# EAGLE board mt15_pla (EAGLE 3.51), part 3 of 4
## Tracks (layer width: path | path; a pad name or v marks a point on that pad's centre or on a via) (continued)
N$24  (via drill 0.61 pad 1.02)
  Top 0.305: 107.62,6.6 107.62,6.97 v107.95,7.3
  Bottom 0.305: J26. 107.63,6.99 v107.95,7.3
N$25  (via drill 0.61 pad 1.02)
  Top 0.305: 73.33,6.6 73.33,6.97 v73.66,7.3
  Bottom 0.305: J17. 73.34,6.99 v73.66,7.3
N$26  (via drill 0.61 pad 1.02)
  Top 0.305: 77.14,6.6 77.14,6.97 v77.47,7.3
  Bottom 0.305: J18. 77.15,6.99 v77.47,7.3
N$27  (via drill 0.61 pad 1.02)
  Top 0.305: 80.95,6.6 80.95,6.97 v81.28,7.3
  Bottom 0.305: J19. 80.96,6.99 v81.28,7.3
N$28  (via drill 0.61 pad 1.02)
  Top 0.305: 84.76,6.6 84.76,6.97 v85.09,7.3
  Bottom 0.305: J20. 84.77,6.99 v85.09,7.3
N$29  (via drill 0.61 pad 1.02)
  Top 0.305: 88.57,6.6 88.57,6.97 v88.9,7.3
  Bottom 0.305: J21. 88.58,6.99 v88.9,7.3
N$30  (via drill 0.61 pad 1.02)
  Top 0.305: 92.38,6.6 92.38,6.97 v92.71,7.3
  Bottom 0.305: J22. 92.39,6.99 v92.71,7.3
N$31  (via drill 0.61 pad 1.02)
  Top 0.305: 96.19,6.6 96.19,6.97 v96.52,7.3
  Bottom 0.305: J23. 96.2,6.99 v96.52,7.3
N$32  (via drill 0.61 pad 1.02)
  Top 0.305: 100,6.6 100,6.97 v100.33,7.3
  Bottom 0.305: J24. 100.01,6.99 v100.33,7.3
N$33  (via drill 0.61 pad 1.02)
  Top 0.305: 103.81,6.6 103.81,6.97 v104.14,7.3
  Bottom 0.305: J25. 103.82,6.99 v104.14,7.3
N$34  (via drill 0.61 pad 1.02)
  Top 0.406: 53.03,12.45 53.03,12.39 v52.7,12.06
  Bottom 0.406: J40. 53.02,12.38 v52.7,12.06
N$35  (via drill 0.61 pad 1.02)
  Top 0.406: 49.23,12.45 49.23,12.39 v48.9,12.06
  Bottom 0.406: J39. 49.21,12.38 v48.9,12.06
N$36  (via drill 0.61 pad 1.02)
  Top 0.406: 45.41,12.45 45.41,12.39 v45.09,12.06
  Bottom 0.406: J38. 45.4,12.38 v45.09,12.06
N$37  (via drill 0.61 pad 1.02)
  Top 0.406: 22.55,12.45 22.55,12.39 v22.23,12.06
  Bottom 0.406: J32. 22.54,12.38 v22.23,12.06
N$38  (via drill 0.61 pad 1.02)
  Top 0.406: 18.75,12.45 18.75,12.39 v18.41,12.06
  Bottom 0.406: J31. 18.73,12.38 v18.41,12.06
N$39  (via drill 0.61 pad 1.02)
  Top 0.406: 14.94,12.45 14.94,12.39 v14.61,12.06
  Bottom 0.406: J30. 14.92,12.38 v14.61,12.06
N$40  (via drill 0.61 pad 1.02)
  Top 0.406: 26.36,12.45 26.36,12.39 v26.04,12.06
  Bottom 0.406: J33. 26.35,12.38 v26.04,12.06
N$41  (via drill 0.61 pad 1.02)
  Top 0.406: 30.18,12.45 30.18,12.39 v29.84,12.06
  Bottom 0.406: J34. 30.16,12.38 v29.84,12.06
N$42  (via drill 0.61 pad 1.02)
  Top 0.406: 33.98,12.45 33.98,12.39 v33.66,12.06
  Bottom 0.406: J35. 33.97,12.38 v33.66,12.06
N$43  (via drill 0.61 pad 1.02)
  Top 0.406: 37.8,12.45 37.8,12.39 v37.47,12.06
  Bottom 0.406: J36. 37.78,12.38 v37.47,12.06
N$44  (via drill 0.61 pad 1.02)
  Top 0.406: 41.6,12.45 41.6,12.39 v41.27,12.06
  Bottom 0.406: J37. 41.59,12.38 v41.27,12.06
N$45  (via drill 0.61 pad 1.02)
  Top 0.305: 105.74,11.81 105.74,11.44 v105.41,11.11
  Bottom 0.305: J52. 105.73,11.43 v105.41,11.11
N$46  (via drill 0.61 pad 1.02)
  Top 0.305: 71.45,11.81 71.12,11.48 v71.12,11.11
  Bottom 0.305: J43. 71.44,11.11 v71.12,11.11
N$47  (via drill 0.61 pad 1.02)
  Top 0.305: 75.26,11.81 74.93,11.48 v74.93,11.11
  Bottom 0.305: J44. 75.25,11.11 v74.93,11.11
N$48  (via drill 0.61 pad 1.02)
  Top 0.305: 79.07,11.81 78.74,11.48 v78.74,11.11
  Bottom 0.305: J45. 79.06,11.11 v78.74,11.11
N$49  (via drill 0.61 pad 1.02)
  Top 0.305: 82.88,11.81 82.88,11.44 v82.55,11.11
  Bottom 0.305: J46. 82.87,11.43 v82.55,11.11
N$50  (via drill 0.61 pad 1.02)
  Top 0.305: 86.69,11.81 86.69,11.44 v86.36,11.11
  Bottom 0.305: J47. 86.68,11.43 v86.36,11.11
N$51  (via drill 0.61 pad 1.02)
  Top 0.305: 90.5,11.81 90.5,11.44 v90.17,11.11
  Bottom 0.305: J48. 90.49,11.43 v90.17,11.11
N$52  (via drill 0.61 pad 1.02)
  Top 0.305: 94.31,11.81 94.31,11.44 v93.98,11.11
  Bottom 0.305: J49. 94.3,11.43 v93.98,11.11
N$53  (via drill 0.61 pad 1.02)
  Top 0.305: 98.12,11.81 98.12,11.44 v97.79,11.11
  Bottom 0.305: J50. 98.11,11.43 v97.79,11.11
N$54  (via drill 0.61 pad 1.02)
  Top 0.305: 101.93,11.81 101.93,11.44 v101.6,11.11
  Bottom 0.305: J51. 101.92,11.43 v101.6,11.11
N$55  (via drill 0.61 pad 1.02)
  Top 0.406: 7.92,14.86 7.92,14.91 v8.26,15.24
  Bottom 0.406: J53. 7.94,14.92 v8.26,15.24
N$56  (via drill 0.61 pad 1.02)
  Top 0.406: 11.73,14.86 11.73,14.91 v12.06,15.24
  Bottom 0.406: J54. 11.75,14.92 v12.06,15.24
N$57  (via drill 0.61 pad 1.02)
  Top 0.406: 15.54,14.86 15.54,14.91 v15.88,15.24
  Bottom 0.406: J55. 15.56,14.92 v15.88,15.24
N$58  (via drill 0.61 pad 1.02)
  Top 0.305: 71.4,14.86 71.4,13.65 71.75,13.65 | 71.75,13.65 75.25,13.65 | 75.25,13.65 79.06,13.65 | 75.21,14.86 75.25,14.82 75.25,13.65 | 79.02,14.86 79.06,14.82 79.06,13.65 | 71.75,13.65 71.12,13.65 v70.17,14.61 | 110.11,14.61 109.16,13.65 105.73,13.65 | 79.06,13.65 82.87,13.65 | 82.87,13.65 86.68,13.65 | 86.68,13.65 90.49,13.65 | 90.49,13.65 94.3,13.65 | 94.3,13.65 98.11,13.65 | 98.11,13.65 101.92,13.65 | 101.92,13.65 105.73,13.65 | 82.83,14.86 82.87,14.86 82.87,13.65 | 86.64,14.86 86.68,14.86 86.68,13.65 | 90.45,14.86 90.49,14.86 90.49,13.65 | 94.26,14.86 94.3,14.86 94.3,13.65 | 98.07,14.86 98.11,14.86 98.11,13.65 | 105.69,14.86 105.73,14.86 105.73,13.65 | 101.88,14.86 101.92,14.86 101.92,13.65
  Bottom 0.305: 6.22,14.92 6.35,14.92 6.35,16.51 10.16,16.51 | 10.16,16.51 13.97,16.51 | 13.97,16.51 17.78,16.51 | 17.78,16.51 21.59,16.51 | 21.59,16.51 25.4,16.51 | 25.4,16.51 29.21,16.51 | 29.21,16.51 33.02,16.51 | 33.02,16.51 36.83,16.51 | 36.83,16.51 40.64,16.51 | 40.64,16.51 44.45,16.51 | 44.45,16.51 48.26,16.51 | 48.26,16.51 52.07,16.51 | 52.07,16.51 55.88,16.51 | 55.88,16.51 59.69,16.51 | 59.69,16.51 63.5,16.51 | 63.37,14.92 63.5,14.92 63.5,16.51 | 59.56,14.92 59.69,14.92 59.69,16.51 | 55.75,14.92 55.88,14.92 55.88,16.51 | 51.94,14.92 52.07,14.92 52.07,16.51 | 48.13,14.92 48.26,14.92 48.26,16.51 | 44.32,14.92 44.45,14.92 44.45,16.51 | 40.51,14.92 40.64,14.92 40.64,16.51 | 36.7,14.92 36.83,14.92 36.83,16.51 | 32.89,14.92 33.02,14.92 33.02,16.51 | 29.08,14.92 29.21,14.92 29.21,16.51 | 25.27,14.92 25.4,14.92 25.4,16.51 | 21.46,14.92 21.59,14.92 21.59,16.51 | 10.03,14.92 10.16,14.92 10.16,16.51 | 13.84,14.92 13.97,14.92 13.97,16.51 | 17.65,14.92 17.78,14.92 17.78,16.51 | 63.5,16.51 68.26,16.51 v70.17,14.61
N$59  (via drill 0.61 pad 1.02)
  Top 0.406: 65.08,14.86 65.08,14.91 v65.41,15.24
  Bottom 0.406: J68. 65.09,14.92 v65.41,15.24
N$60  (via drill 0.61 pad 1.02)
  Top 0.406: 61.27,14.86 61.27,14.91 v61.59,15.24
  Bottom 0.406: J67. 61.28,14.92 v61.59,15.24
N$61  (via drill 0.61 pad 1.02)
  Top 0.406: 57.45,14.86 57.45,14.91 v57.78,15.24
  Bottom 0.406: J66. 57.47,14.92 v57.78,15.24
N$62  (via drill 0.61 pad 1.02)
  Top 0.406: 53.65,14.86 53.65,14.91 v53.98,15.24
  Bottom 0.406: J65. 53.66,14.92 v53.98,15.24
N$63  (via drill 0.61 pad 1.02)
  Top 0.406: 49.84,14.86 49.84,14.91 v50.16,15.24
  Bottom 0.406: J64. 49.85,14.92 v50.16,15.24
N$64  (via drill 0.61 pad 1.02)
  Top 0.406: 26.98,14.86 26.98,14.91 v27.3,15.24
  Bottom 0.406: J58. 26.99,14.92 v27.3,15.24
N$65  (via drill 0.61 pad 1.02)
  Top 0.406: 23.16,14.86 23.16,14.91 v23.5,15.24
  Bottom 0.406: J57. 23.18,14.92 v23.5,15.24
N$66  (via drill 0.61 pad 1.02)
  Top 0.406: 19.36,14.86 19.36,14.91 v19.68,15.24
  Bottom 0.406: J56. 19.37,14.92 v19.68,15.24
N$67  (via drill 0.61 pad 1.02)
  Top 0.406: 30.79,14.86 30.79,14.91 v31.11,15.24
  Bottom 0.406: J59. 30.8,14.92 v31.11,15.24
N$68  (via drill 0.61 pad 1.02)
  Top 0.406: 34.59,14.86 34.59,14.91 v34.92,15.24
  Bottom 0.406: J60. 34.61,14.92 v34.92,15.24
N$69  (via drill 0.61 pad 1.02)
  Top 0.406: 38.41,14.86 38.41,14.91 v38.73,15.24
  Bottom 0.406: J61. 38.42,14.92 v38.73,15.24
N$70  (via drill 0.61 pad 1.02)
  Top 0.406: 42.22,14.86 42.22,14.91 v42.55,15.24
  Bottom 0.406: J62. 42.23,14.92 v42.55,15.24
N$71  (via drill 0.61 pad 1.02)
  Top 0.406: 46.02,14.86 46.02,14.91 v46.35,15.24
  Bottom 0.406: J63. 46.04,14.92 v46.35,15.24
N$72  (via drill 0.61 pad 1.02)
  Top 0.305: 107.62,14.86 107.62,15.23 v107.95,15.56
  Bottom 0.305: J78. 107.63,15.24 v107.95,15.56
N$73  (via drill 0.61 pad 1.02)
  Top 0.305: 73.33,14.86 73.33,15.23 v73.66,15.56
  Bottom 0.305: J69. 73.34,15.24 v73.66,15.56
N$74  (via drill 0.61 pad 1.02)
  Top 0.305: 77.14,14.86 77.14,15.23 v77.47,15.56
  Bottom 0.305: J70. 77.15,15.24 v77.47,15.56
N$75  (via drill 0.61 pad 1.02)
  Top 0.305: 80.95,14.86 80.95,15.23 v81.28,15.56
  Bottom 0.305: J71. 80.96,15.24 v81.28,15.56
N$76  (via drill 0.61 pad 1.02)
  Top 0.305: 84.76,14.86 84.76,15.23 v85.09,15.56
  Bottom 0.305: J72. 84.77,15.24 v85.09,15.56
N$77  (via drill 0.61 pad 1.02)
  Top 0.305: 88.57,14.86 88.57,15.23 v88.9,15.56
  Bottom 0.305: J73. 88.58,15.24 v88.9,15.56
N$78  (via drill 0.61 pad 1.02)
  Top 0.305: 92.38,14.86 92.38,15.23 v92.71,15.56
  Bottom 0.305: J74. 92.39,15.24 v92.71,15.56
N$79  (via drill 0.61 pad 1.02)
  Top 0.305: 96.19,14.86 96.19,15.23 v96.52,15.56
  Bottom 0.305: J75. 96.2,15.24 v96.52,15.56
N$80  (via drill 0.61 pad 1.02)
  Top 0.305: 100,14.86 100,15.23 v100.33,15.56
  Bottom 0.305: J76. 100.01,15.24 v100.33,15.56
N$81  (via drill 0.61 pad 1.02)
  Top 0.305: 103.81,14.86 103.81,15.23 v104.14,15.56
  Bottom 0.305: J77. 103.82,15.24 v104.14,15.56
N$82  (via drill 0.61 pad 1.02)
  Top 0.406: 3.5,20.7 3.5,20.65 v3.17,20.32
  Bottom 0.406: J79. 3.49,20.64 v3.17,20.32
N$83  (via drill 0.61 pad 1.02)
  Top 0.406: 7.32,20.7 7.32,20.65 v6.99,20.32
  Bottom 0.406: J80. 7.3,20.64 v6.99,20.32
N$84  (via drill 0.61 pad 1.02)
  Top 0.406: 11.12,20.7 11.12,20.65 v10.79,20.32
  Bottom 0.406: J81. 11.11,20.64 v10.79,20.32
N$85  (via drill 0.61 pad 1.02)
  Top 0.305: 110.11,20.32 109.16,21.27 107.63,21.27 | 73.34,21.27 77.15,21.27 | 77.15,21.27 80.96,21.27 | 80.96,21.27 84.77,21.27 | 84.77,21.27 88.58,21.27 | 88.58,21.27 92.39,21.27 | 92.39,21.27 96.2,21.27 | 96.2,21.27 100.01,21.27 | 100.01,21.27 103.82,21.27 | 103.82,21.27 107.63,21.27 | v70.17,21.27 73.34,21.27 | 107.67,20.07 107.63,20.07 107.63,21.27 | 103.86,20.07 103.82,20.07 103.82,21.27 | 73.38,20.07 73.34,20.07 73.34,21.27 | 77.19,20.07 77.15,20.07 77.15,21.27 | 81,20.07 80.96,20.07 80.96,21.27 | 84.81,20.07 84.77,20.07 84.77,21.27 | 88.62,20.07 88.58,20.07 88.58,21.27 | 92.43,20.07 92.39,20.07 92.39,21.27 | 96.24,20.07 96.2,20.07 96.2,21.27 | 100.05,20.07 100.01,20.07 100.01,21.27
  Bottom 0.305: 5.21,20.64 5.08,20.64 5.08,19.05 8.89,19.05 | 8.89,19.05 12.7,19.05 | 12.7,19.05 16.51,19.05 | 16.51,19.05 20.32,19.05 | 20.32,19.05 24.13,19.05 | 24.13,19.05 27.94,19.05 | 27.94,19.05 31.75,19.05 | 31.75,19.05 35.56,19.05 | 35.56,19.05 39.37,19.05 | 39.37,19.05 43.18,19.05 | 43.18,19.05 46.99,19.05 | 46.99,19.05 50.8,19.05 | 50.8,19.05 54.61,19.05 | 54.61,19.05 58.42,19.05 | 58.42,19.05 62.23,19.05 | 9.02,20.64 8.89,20.64 8.89,19.05 | 12.83,20.64 12.7,20.64 12.7,19.05 | 16.64,20.64 16.51,20.64 16.51,19.05 | 20.45,20.64 20.32,20.64 20.32,19.05 | 24.26,20.64 24.13,20.64 24.13,19.05 | 28.07,20.64 27.94,20.64 27.94,19.05 | 31.88,20.64 31.75,20.64 31.75,19.05 | 35.69,20.64 35.56,20.64 35.56,19.05 | 39.5,20.64 39.37,20.64 39.37,19.05 | 43.31,20.64 43.18,20.64 43.18,19.05 | 47.12,20.64 46.99,20.64 46.99,19.05 | 50.93,20.64 50.8,20.64 50.8,19.05 | 62.36,20.64 62.23,20.64 62.23,19.05 | 58.55,20.64 58.42,20.64 58.42,19.05 | 54.74,20.64 54.61,20.64 54.61,19.05 | 62.23,19.05 67.94,19.05 v70.17,21.27
N$86  (via drill 0.61 pad 1.02)
  Top 0.406: 60.66,20.7 60.66,20.65 v60.33,20.32
  Bottom 0.406: J94. 60.64,20.64 v60.33,20.32
N$87  (via drill 0.61 pad 1.02)
  Top 0.406: 56.84,20.7 56.84,20.65 v56.52,20.32
  Bottom 0.406: J93. 56.83,20.64 v56.52,20.32
N$88  (via drill 0.61 pad 1.02)
  Top 0.406: 53.03,20.7 53.03,20.65 v52.7,20.32
  Bottom 0.406: J92. 53.02,20.64 v52.7,20.32
N$89  (via drill 0.61 pad 1.02)
  Top 0.406: 49.23,20.7 49.23,20.65 v48.9,20.32
  Bottom 0.406: J91. 49.21,20.64 v48.9,20.32
N$90  (via drill 0.61 pad 1.02)
  Top 0.406: 45.41,20.7 45.41,20.65 v45.09,20.32
  Bottom 0.406: J90. 45.4,20.64 v45.09,20.32
N$91  (via drill 0.61 pad 1.02)
  Top 0.406: 22.55,20.7 22.55,20.65 v22.23,20.32
  Bottom 0.406: J84. 22.54,20.64 v22.23,20.32
N$92  (via drill 0.61 pad 1.02)
  Top 0.406: 18.75,20.7 18.75,20.65 v18.41,20.32
  Bottom 0.406: J83. 18.73,20.64 v18.41,20.32
N$93  (via drill 0.61 pad 1.02)
  Top 0.406: 14.94,20.7 14.94,20.65 v14.61,20.32
  Bottom 0.406: J82. 14.92,20.64 v14.61,20.32
N$94  (via drill 0.61 pad 1.02)
  Top 0.406: 26.36,20.7 26.36,20.65 v26.04,20.32
  Bottom 0.406: J85. 26.35,20.64 v26.04,20.32
N$95  (via drill 0.61 pad 1.02)
  Top 0.406: 30.18,20.7 30.18,20.65 v29.84,20.32
  Bottom 0.406: J86. 30.16,20.64 v29.84,20.32
N$96  (via drill 0.61 pad 1.02)
  Top 0.406: 33.98,20.7 33.98,20.65 v33.66,20.32
  Bottom 0.406: J87. 33.97,20.64 v33.66,20.32
N$97  (via drill 0.61 pad 1.02)
  Top 0.406: 37.8,20.7 37.8,20.65 v37.47,20.32
  Bottom 0.406: J88. 37.78,20.64 v37.47,20.32
N$98  (via drill 0.61 pad 1.02)
  Top 0.406: 41.6,20.7 41.6,20.65 v41.27,20.32
  Bottom 0.406: J89. 41.59,20.64 v41.27,20.32
N$99  (via drill 0.61 pad 1.02)
  Top 0.305: 105.74,20.07 105.74,19.7 v105.41,19.37
  Bottom 0.305: J104. 105.73,19.68 v105.41,19.37
N$100  (via drill 0.61 pad 1.02)
  Top 0.305: 71.45,20.07 71.45,19.7 v71.12,19.37
  Bottom 0.305: J95. 71.44,19.68 v71.12,19.37
N$101  (via drill 0.61 pad 1.02)
  Top 0.305: 75.26,20.07 75.26,19.7 v74.93,19.37
  Bottom 0.305: J96. 75.25,19.68 v74.93,19.37
N$102  (via drill 0.61 pad 1.02)
  Top 0.305: 79.07,20.07 79.07,19.7 v78.74,19.37
  Bottom 0.305: J97. 79.06,19.68 v78.74,19.37
N$103  (via drill 0.61 pad 1.02)
  Top 0.305: 82.88,20.07 82.88,19.7 v82.55,19.37
  Bottom 0.305: J98. 82.87,19.68 v82.55,19.37
N$104  (via drill 0.61 pad 1.02)
  Top 0.305: 86.69,20.07 86.69,19.7 v86.36,19.37
  Bottom 0.305: J99. 86.68,19.68 v86.36,19.37
N$105  (via drill 0.61 pad 1.02)
  Top 0.305: 90.5,20.07 90.5,19.7 v90.17,19.37
  Bottom 0.305: J100. 90.49,19.68 v90.17,19.37
N$106  (via drill 0.61 pad 1.02)
  Top 0.305: 94.31,20.07 94.31,19.7 v93.98,19.37
  Bottom 0.305: J101. 94.3,19.68 v93.98,19.37
N$107  (via drill 0.61 pad 1.02)
  Top 0.305: 98.12,20.07 98.12,19.7 v97.79,19.37
  Bottom 0.305: J102. 98.11,19.68 v97.79,19.37
N$108  (via drill 0.61 pad 1.02)
  Top 0.305: v101.6,19.37 101.92,19.37 101.93,19.38 101.93,20.07
  Bottom 0.305: J103. 101.92,19.68 v101.6,19.37
N$109  (via drill 0.61 pad 1.02)
  Top 0.406: 7.92,23.11 7.92,23.16 v8.26,23.5
  Bottom 0.406: J105. 7.94,23.18 v8.26,23.5
N$110  (via drill 0.61 pad 1.02)
  Top 0.406: 11.73,23.11 11.73,23.16 v12.06,23.5
  Bottom 0.406: J106. 11.75,23.18 v12.06,23.5
N$111  (via drill 0.61 pad 1.02)
  Top 0.406: 15.54,23.11 15.54,23.16 v15.88,23.5
  Bottom 0.406: J107. 15.56,23.18 v15.88,23.5
N$112  (via drill 0.61 pad 1.02)
  Top 0.305: 110.11,22.86 109.16,21.91 105.73,21.91 | 71.44,21.91 71.12,21.91 v70.17,22.86 | 71.44,21.91 75.25,21.91 | 75.25,21.91 79.06,21.91 | 79.06,21.91 82.87,21.91 | 82.87,21.91 86.68,21.91 | 86.68,21.91 90.49,21.91 | 90.49,21.91 94.3,21.91 | 94.3,21.91 98.11,21.91 | 98.11,21.91 101.92,21.91 | 101.92,21.91 105.73,21.91 | 105.69,23.11 105.73,23.11 105.73,21.91 | 94.26,23.11 94.3,23.11 94.3,21.91 | 90.45,23.11 90.49,23.11 90.49,21.91 | 98.07,23.11 98.11,23.11 98.11,21.91 | 101.88,23.11 101.92,23.11 101.92,21.91 | 86.64,23.11 86.68,23.11 86.68,21.91 | 82.83,23.11 82.87,23.11 82.87,21.91 | 79.02,23.11 79.06,23.11 79.06,21.91 | 75.21,23.11 75.25,23.11 75.25,21.91 | 71.4,23.11 71.44,23.11 71.44,21.91
  Bottom 0.305: 6.22,23.18 6.35,23.18 6.35,24.77 10.16,24.77 | 10.16,24.77 13.97,24.77 | 13.97,24.77 17.78,24.77 | 17.78,24.77 21.59,24.77 | 21.59,24.77 25.4,24.77 | 25.4,24.77 29.21,24.77 | 29.21,24.77 33.02,24.77 | 33.02,24.77 36.83,24.77 | 36.83,24.77 40.64,24.77 | 40.64,24.77 44.45,24.77 | 44.45,24.77 48.26,24.77 | 48.26,24.77 52.07,24.77 | 52.07,24.77 55.88,24.77 | 55.88,24.77 59.69,24.77 | 59.69,24.77 63.5,24.77 | 63.37,23.18 63.5,23.18 63.5,24.77 | 59.56,23.18 59.69,23.18 59.69,24.77 | 55.75,23.18 55.88,23.18 55.88,24.77 | 51.94,23.18 52.07,23.18 52.07,24.77 | 48.13,23.18 48.26,23.18 48.26,24.77 | 44.32,23.18 44.45,23.18 44.45,24.77 | 40.51,23.18 40.64,23.18 40.64,24.77 | 36.7,23.18 36.83,23.18 36.83,24.77 | 32.89,23.18 33.02,23.18 33.02,24.77 | 29.08,23.18 29.21,23.18 29.21,24.77 | 25.27,23.18 25.4,23.18 25.4,24.77 | 21.46,23.18 21.59,23.18 21.59,24.77 | 17.65,23.18 17.78,23.18 17.78,24.77 | 13.84,23.18 13.97,23.18 13.97,24.77 | 10.03,23.18 10.16,23.18 10.16,24.77 | 63.5,24.77 68.26,24.77 v70.17,22.86
N$113  (via drill 0.61 pad 1.02)
  Top 0.406: 65.08,23.11 65.08,23.16 v65.41,23.5
  Bottom 0.406: J120. 65.09,23.18 v65.41,23.5
N$114  (via drill 0.61 pad 1.02)
  Top 0.406: 61.27,23.11 61.27,23.16 v61.59,23.5
  Bottom 0.406: J119. 61.28,23.18 v61.59,23.5
N$115  (via drill 0.61 pad 1.02)
  Top 0.406: 57.45,23.11 57.45,23.16 v57.78,23.5
  Bottom 0.406: J118. 57.47,23.18 v57.78,23.5
N$116  (via drill 0.61 pad 1.02)
  Top 0.406: 53.65,23.11 53.65,23.16 v53.98,23.5
  Bottom 0.406: J117. 53.66,23.18 v53.98,23.5
N$117  (via drill 0.61 pad 1.02)
  Top 0.406: 49.84,23.11 49.84,23.16 v50.16,23.5
  Bottom 0.406: J116. 49.85,23.18 v50.16,23.5
N$118  (via drill 0.61 pad 1.02)
  Top 0.406: 26.98,23.11 26.98,23.16 v27.3,23.5
  Bottom 0.406: J110. 26.99,23.18 v27.3,23.5
N$119  (via drill 0.61 pad 1.02)
  Top 0.406: 23.16,23.11 23.16,23.16 v23.5,23.5
  Bottom 0.406: J109. 23.18,23.18 v23.5,23.5
N$120  (via drill 0.61 pad 1.02)
  Top 0.406: 19.36,23.11 19.36,23.16 v19.68,23.5
  Bottom 0.406: J108. 19.37,23.18 v19.68,23.5
N$121  (via drill 0.61 pad 1.02)
  Top 0.406: 30.79,23.11 30.79,23.16 v31.11,23.5
  Bottom 0.406: J111. 30.8,23.18 v31.11,23.5
N$122  (via drill 0.61 pad 1.02)
  Top 0.406: 34.59,23.11 34.59,23.16 v34.92,23.5
  Bottom 0.406: J112. 34.61,23.18 v34.92,23.5
N$123  (via drill 0.61 pad 1.02)
  Top 0.406: 38.41,23.11 38.41,23.16 v38.73,23.5
  Bottom 0.406: J113. 38.42,23.18 v38.73,23.5
N$124  (via drill 0.61 pad 1.02)
  Top 0.406: 42.22,23.11 42.22,23.16 v42.55,23.5
  Bottom 0.406: J114. 42.23,23.18 v42.55,23.5
N$125  (via drill 0.61 pad 1.02)
  Top 0.406: 46.02,23.11 46.02,23.16 v46.35,23.5
  Bottom 0.406: J115. 46.04,23.18 v46.35,23.5
N$126  (via drill 0.61 pad 1.02)
  Top 0.305: 107.62,23.11 107.62,23.48 v107.95,23.81
  Bottom 0.305: J130. 107.63,23.5 v107.95,23.81
N$127  (via drill 0.61 pad 1.02)
  Top 0.305: 73.33,23.11 73.33,23.48 v73.66,23.81
  Bottom 0.305: J121. 73.34,23.5 v73.66,23.81
N$128  (via drill 0.61 pad 1.02)
  Top 0.305: 77.14,23.11 77.14,23.48 v77.47,23.81
  Bottom 0.305: J122. 77.15,23.5 v77.47,23.81
N$129  (via drill 0.61 pad 1.02)
  Top 0.305: 80.95,23.11 80.95,23.48 v81.28,23.81
  Bottom 0.305: J123. 80.96,23.5 v81.28,23.81
N$130  (via drill 0.61 pad 1.02)
  Top 0.305: 84.76,23.11 84.76,23.48 v85.09,23.81
  Bottom 0.305: J124. 84.77,23.5 v85.09,23.81
N$131  (via drill 0.61 pad 1.02)
  Top 0.305: 88.57,23.11 88.57,23.48 v88.9,23.81
  Bottom 0.305: J125. 88.58,23.5 v88.9,23.81
N$132  (via drill 0.61 pad 1.02)
  Top 0.305: 92.38,23.11 92.38,23.48 v92.71,23.81
  Bottom 0.305: J126. 92.39,23.5 v92.71,23.81
N$133  (via drill 0.61 pad 1.02)
  Top 0.305: 96.19,23.11 96.19,23.48 v96.52,23.81
  Bottom 0.305: J127. 96.2,23.5 v96.52,23.81
N$134  (via drill 0.61 pad 1.02)
  Top 0.305: 100,23.11 100,23.48 v100.33,23.81
  Bottom 0.305: J128. 100.01,23.5 v100.33,23.81
N$135  (via drill 0.61 pad 1.02)
  Top 0.305: 103.81,23.11 103.81,23.48 v104.14,23.81
  Bottom 0.305: J129. 103.82,23.5 v104.14,23.81
N$136  (via drill 0.61 pad 1.02)
  Top 0.406: 3.5,28.96 3.5,28.91 v3.17,28.57
  Bottom 0.406: J131. 3.49,28.89 v3.17,28.57
N$137  (via drill 0.61 pad 1.02)
  Top 0.406: 7.32,28.96 7.32,28.91 v6.99,28.57
  Bottom 0.406: J132. 7.3,28.89 v6.99,28.57
N$138  (via drill 0.61 pad 1.02)
  Top 0.406: 11.12,28.96 11.12,28.91 v10.79,28.57
  Bottom 0.406: J133. 11.11,28.89 v10.79,28.57
N$139  (via drill 0.61 pad 1.02)
  Top 0.305: 110.11,28.57 109.16,29.53 107.63,29.53 | 73.34,29.53 77.15,29.53 | 77.15,29.53 80.96,29.53 | 80.96,29.53 84.77,29.53 | 84.77,29.53 88.58,29.53 | 88.58,29.53 92.39,29.53 | 92.39,29.53 96.2,29.53 | 96.2,29.53 100.01,29.53 | 100.01,29.53 103.82,29.53 | 103.82,29.53 107.63,29.53 | v70.17,29.53 73.34,29.53 | 107.67,28.32 107.63,28.32 107.63,29.53 | 103.86,28.32 103.82,28.32 103.82,29.53 | 100.05,28.32 100.01,28.32 100.01,29.53 | 96.24,28.32 96.2,28.32 96.2,29.53 | 92.43,28.32 92.39,28.32 92.39,29.53 | 73.38,28.32 73.34,28.32 73.34,29.53 | 77.19,28.32 77.15,28.32 77.15,29.53 | 81,28.32 80.96,28.32 80.96,29.53 | 84.81,28.32 84.77,28.32 84.77,29.53 | 88.62,28.32 88.58,28.32 88.58,29.53
  Bottom 0.305: 5.21,28.89 5.08,28.89 5.08,27.3 8.89,27.3 | 8.89,27.3 12.7,27.3 | 12.7,27.3 16.51,27.3 | 16.51,27.3 20.32,27.3 | 20.32,27.3 24.13,27.3 | 24.13,27.3 27.94,27.3 | 27.94,27.3 31.75,27.3 | 31.75,27.3 35.56,27.3 | 35.56,27.3 39.37,27.3 | 39.37,27.3 43.18,27.3 | 43.18,27.3 46.99,27.3 | 46.99,27.3 50.8,27.3 | 50.8,27.3 54.61,27.3 | 54.61,27.3 58.42,27.3 | 58.42,27.3 62.23,27.3 | 9.02,28.89 8.89,28.89 8.89,27.3 | 12.83,28.89 12.7,28.89 12.7,27.3 | 16.64,28.89 16.51,28.89 16.51,27.3 | 20.45,28.89 20.32,28.89 20.32,27.3 | 24.26,28.89 24.13,28.89 24.13,27.3 | 28.07,28.89 27.94,28.89 27.94,27.3 | 31.88,28.89 31.75,28.89 31.75,27.3 | 35.69,28.89 35.56,28.89 35.56,27.3 | 39.5,28.89 39.37,28.89 39.37,27.3 | 43.31,28.89 43.18,28.89 43.18,27.3 | 47.12,28.89 46.99,28.89 46.99,27.3 | 50.93,28.89 50.8,28.89 50.8,27.3 | 54.74,28.89 54.61,28.89 54.61,27.3 | 58.55,28.89 58.42,28.89 58.42,27.3 | 62.36,28.89 62.23,28.89 62.23,27.3 | 62.23,27.3 67.94,27.3 v70.17,29.53
N$140  (via drill 0.61 pad 1.02)
  Top 0.406: 60.66,28.96 60.66,28.91 v60.33,28.57
  Bottom 0.406: J146. 60.64,28.89 v60.33,28.57
N$141  (via drill 0.61 pad 1.02)
  Top 0.406: 56.84,28.96 56.84,28.91 v56.52,28.57
  Bottom 0.406: J145. 56.83,28.89 v56.52,28.57
N$142  (via drill 0.61 pad 1.02)
  Top 0.406: 53.03,28.96 53.03,28.91 v52.7,28.57
  Bottom 0.406: J144. 53.02,28.89 v52.7,28.57
N$143  (via drill 0.61 pad 1.02)
  Top 0.406: 49.23,28.96 49.23,28.91 v48.9,28.57
  Bottom 0.406: J143. 49.21,28.89 v48.9,28.57
N$144  (via drill 0.61 pad 1.02)
  Top 0.406: 45.41,28.96 45.41,28.91 v45.09,28.57
  Bottom 0.406: J142. 45.4,28.89 v45.09,28.57
N$145  (via drill 0.61 pad 1.02)
  Top 0.406: 22.55,28.96 22.55,28.91 v22.23,28.57
  Bottom 0.406: J136. 22.54,28.89 v22.23,28.57
N$146  (via drill 0.61 pad 1.02)
  Top 0.406: 18.75,28.96 18.75,28.91 v18.41,28.57
  Bottom 0.406: J135. 18.73,28.89 v18.41,28.57
N$147  (via drill 0.61 pad 1.02)
  Top 0.406: 14.94,28.96 14.94,28.91 v14.61,28.57
  Bottom 0.406: J134. 14.92,28.89 v14.61,28.57
N$148  (via drill 0.61 pad 1.02)
  Top 0.406: 26.36,28.96 26.36,28.91 v26.04,28.57
  Bottom 0.406: J137. 26.35,28.89 v26.04,28.57
N$149  (via drill 0.61 pad 1.02)
  Top 0.406: 30.18,28.96 30.18,28.91 v29.84,28.57
  Bottom 0.406: J138. 30.16,28.89 v29.84,28.57
N$150  (via drill 0.61 pad 1.02)
  Top 0.406: 33.98,28.96 33.98,28.91 v33.66,28.57
  Bottom 0.406: J139. 33.97,28.89 v33.66,28.57
N$151  (via drill 0.61 pad 1.02)
  Top 0.406: 37.8,28.96 37.8,28.91 v37.47,28.57
  Bottom 0.406: J140. 37.78,28.89 v37.47,28.57
N$152  (via drill 0.61 pad 1.02)
  Top 0.406: 41.6,28.96 41.6,28.91 v41.27,28.57
  Bottom 0.406: J141. 41.59,28.89 v41.27,28.57
N$153  (via drill 0.61 pad 1.02)
  Top 0.305: 105.74,28.32 105.74,27.95 v105.41,27.62
  Bottom 0.305: J156. 105.73,27.94 v105.41,27.62
N$154  (via drill 0.61 pad 1.02)
  Top 0.305: 71.45,28.32 71.45,27.95 v71.12,27.62
  Bottom 0.305: J147. 71.44,27.94 v71.12,27.62
N$155  (via drill 0.61 pad 1.02)
  Top 0.305: 75.26,28.32 75.26,27.95 v74.93,27.62
  Bottom 0.305: J148. 75.25,27.94 v74.93,27.62
N$156  (via drill 0.61 pad 1.02)
  Top 0.305: 79.07,28.32 79.07,27.95 v78.74,27.62
  Bottom 0.305: J149. 79.06,27.94 v78.74,27.62
N$157  (via drill 0.61 pad 1.02)
  Top 0.305: 82.88,28.32 82.88,27.95 v82.55,27.62
  Bottom 0.305: J150. 82.87,27.94 v82.55,27.62
N$158  (via drill 0.61 pad 1.02)
  Top 0.305: 86.69,28.32 86.69,27.95 v86.36,27.62
  Bottom 0.305: J151. 86.68,27.94 v86.36,27.62
N$159  (via drill 0.61 pad 1.02)
  Top 0.305: 90.5,28.32 90.5,27.95 v90.17,27.62
  Bottom 0.305: J152. 90.49,27.94 v90.17,27.62
N$160  (via drill 0.61 pad 1.02)
  Top 0.305: 94.31,28.32 94.31,27.95 v93.98,27.62
  Bottom 0.305: J153. 94.3,27.94 v93.98,27.62
N$161  (via drill 0.61 pad 1.02)
  Top 0.305: 98.12,28.32 98.12,27.95 v97.79,27.62
  Bottom 0.305: J154. 98.11,27.94 v97.79,27.62
N$162  (via drill 0.61 pad 1.02)
  Top 0.305: 101.93,28.32 101.93,27.95 v101.6,27.62
  Bottom 0.305: J155. 101.92,27.94 v101.6,27.62
N$163  (via drill 0.61 pad 1.02)
  Top 0.406: 7.92,31.37 7.92,31.42 v8.26,31.75
  Bottom 0.406: J157. 7.94,31.43 v8.26,31.75
N$164  (via drill 0.61 pad 1.02)
  Top 0.406: 11.73,31.37 11.73,31.42 v12.06,31.75
  Bottom 0.406: J158. 11.75,31.43 v12.06,31.75
N$165  (via drill 0.61 pad 1.02)
  Top 0.406: 15.54,31.37 15.54,31.42 v15.88,31.75
  Bottom 0.406: J159. 15.56,31.43 v15.88,31.75
N$166  (via drill 0.61 pad 1.02)
  Top 0.305: 110.11,31.11 109.16,30.16 105.73,30.16 | 71.44,30.16 71.12,30.16 v70.17,31.11 | 71.44,30.16 75.25,30.16 | 75.25,30.16 79.06,30.16 | 79.06,30.16 82.87,30.16 | 82.87,30.16 86.68,30.16 | 86.68,30.16 90.49,30.16 | 90.49,30.16 94.3,30.16 | 94.3,30.16 98.11,30.16 | 98.11,30.16 101.92,30.16 | 101.92,30.16 105.73,30.16 | 105.69,31.37 105.73,31.37 105.73,30.16 | 90.45,31.37 90.49,31.37 90.49,30.16 | 94.26,31.37 94.3,31.37 94.3,30.16 | 98.07,31.37 98.11,31.37 98.11,30.16 | 101.88,31.37 101.92,31.37 101.92,30.16 | 86.64,31.37 86.68,31.37 86.68,30.16 | 82.83,31.37 82.87,31.37 82.87,30.16 | 79.02,31.37 79.06,31.37 79.06,30.16 | 75.21,31.37 75.25,31.37 75.25,30.16 | 71.4,31.37 71.44,31.37 71.44,30.16
  Bottom 0.305: 6.22,31.43 6.35,31.43 6.35,33.02 10.16,33.02 | 10.16,33.02 13.97,33.02 | 13.97,33.02 17.78,33.02 | 17.78,33.02 21.59,33.02 | 21.59,33.02 25.4,33.02 | 25.4,33.02 29.21,33.02 | 29.21,33.02 33.02,33.02 | 33.02,33.02 36.83,33.02 | 36.83,33.02 40.64,33.02 | 40.64,33.02 44.45,33.02 | 44.45,33.02 48.26,33.02 | 48.26,33.02 52.07,33.02 | 52.07,33.02 55.88,33.02 | 55.88,33.02 59.69,33.02 | 59.69,33.02 63.5,33.02 | 10.03,31.43 10.16,31.43 10.16,33.02 | 13.84,31.43 13.97,31.43 13.97,33.02 | 17.65,31.43 17.78,31.43 17.78,33.02 | 21.46,31.43 21.59,31.43 21.59,33.02 | 48.13,31.43 48.26,31.43 48.26,33.02 | 44.32,31.43 44.45,31.43 44.45,33.02 | 40.51,31.43 40.64,31.43 40.64,33.02 | 36.7,31.43 36.83,31.43 36.83,33.02 | 32.89,31.43 33.02,31.43 33.02,33.02 | 29.08,31.43 29.21,31.43 29.21,33.02 | 25.27,31.43 25.4,31.43 25.4,33.02 | 63.37,31.43 63.5,31.43 63.5,33.02 | 59.56,31.43 59.69,31.43 59.69,33.02 | 55.75,31.43 55.88,31.43 55.88,33.02 | 51.94,31.43 52.07,31.43 52.07,33.02 | 63.5,33.02 68.26,33.02 v70.17,31.11
N$167  (via drill 0.61 pad 1.02)
  Top 0.406: 65.08,31.37 65.08,31.42 v65.41,31.75
  Bottom 0.406: J172. 65.09,31.43 v65.41,31.75
N$168  (via drill 0.61 pad 1.02)
  Top 0.406: 61.27,31.37 61.27,31.42 v61.59,31.75
  Bottom 0.406: J171. 61.28,31.43 v61.59,31.75
N$169  (via drill 0.61 pad 1.02)
  Top 0.406: 57.45,31.37 57.45,31.42 v57.78,31.75
  Bottom 0.406: J170. 57.47,31.43 v57.78,31.75
N$170  (via drill 0.61 pad 1.02)
  Top 0.406: 53.65,31.37 53.65,31.42 v53.98,31.75
  Bottom 0.406: J169. 53.66,31.43 v53.98,31.75
N$171  (via drill 0.61 pad 1.02)
  Top 0.406: 49.84,31.37 49.84,31.42 v50.16,31.75
  Bottom 0.406: J168. 49.85,31.43 v50.16,31.75
N$172  (via drill 0.61 pad 1.02)
  Top 0.406: 26.98,31.37 26.98,31.42 v27.3,31.75
  Bottom 0.406: J162. 26.99,31.43 v27.3,31.75
N$173  (via drill 0.61 pad 1.02)
  Top 0.406: 23.16,31.37 23.16,31.42 v23.5,31.75
  Bottom 0.406: J161. 23.18,31.43 v23.5,31.75
N$174  (via drill 0.61 pad 1.02)
  Top 0.406: 19.36,31.37 19.36,31.42 v19.68,31.75
  Bottom 0.406: J160. 19.37,31.43 v19.68,31.75
N$175  (via drill 0.61 pad 1.02)
  Top 0.406: 30.79,31.37 30.79,31.42 v31.11,31.75
  Bottom 0.406: J163. 30.8,31.43 v31.11,31.75
N$176  (via drill 0.61 pad 1.02)
  Top 0.406: 34.59,31.37 34.59,31.42 v34.92,31.75
  Bottom 0.406: J164. 34.61,31.43 v34.92,31.75
N$177  (via drill 0.61 pad 1.02)
  Top 0.406: 38.41,31.37 38.41,31.42 v38.73,31.75
  Bottom 0.406: J165. 38.42,31.43 v38.73,31.75
N$178  (via drill 0.61 pad 1.02)
  Top 0.406: 42.22,31.37 42.22,31.42 v42.55,31.75
  Bottom 0.406: J166. 42.23,31.43 v42.55,31.75
N$179  (via drill 0.61 pad 1.02)
  Top 0.406: 46.02,31.37 46.02,31.42 v46.35,31.75
  Bottom 0.406: J167. 46.04,31.43 v46.35,31.75
N$180  (via drill 0.61 pad 1.02)
  Top 0.305: 107.62,31.37 107.62,31.74 v107.95,32.07
  Bottom 0.305: J182. 107.63,31.75 v107.95,32.07
N$181  (via drill 0.61 pad 1.02)
  Top 0.305: 73.33,31.37 73.33,31.74 v73.66,32.07
  Bottom 0.305: J173. 73.34,31.75 v73.66,32.07
N$182  (via drill 0.61 pad 1.02)
  Top 0.305: 77.14,31.37 77.14,31.74 v77.47,32.07
  Bottom 0.305: J174. 77.15,31.75 v77.47,32.07
N$183  (via drill 0.61 pad 1.02)
  Top 0.305: 80.95,31.37 80.95,31.74 v81.28,32.07
  Bottom 0.305: J175. 80.96,31.75 v81.28,32.07
N$184  (via drill 0.61 pad 1.02)
  Top 0.305: 84.76,31.37 84.76,31.74 v85.09,32.07
  Bottom 0.305: J176. 84.77,31.75 v85.09,32.07
N$185  (via drill 0.61 pad 1.02)
  Top 0.305: 88.57,31.37 88.57,31.74 v88.9,32.07
  Bottom 0.305: J177. 88.58,31.75 v88.9,32.07
N$186  (via drill 0.61 pad 1.02)
  Top 0.305: 92.38,31.37 92.38,31.74 v92.71,32.07
  Bottom 0.305: J178. 92.39,31.75 v92.71,32.07
N$187  (via drill 0.61 pad 1.02)
  Top 0.305: 96.19,31.37 96.19,31.74 v96.52,32.07
  Bottom 0.305: J179. 96.2,31.75 v96.52,32.07
N$188  (via drill 0.61 pad 1.02)
  Top 0.305: 100,31.37 100,31.74 v100.33,32.07
  Bottom 0.305: J180. 100.01,31.75 v100.33,32.07
N$189  (via drill 0.61 pad 1.02)
  Top 0.305: 103.81,31.37 103.81,31.74 v104.14,32.07
  Bottom 0.305: J181. 103.82,31.75 v104.14,32.07
N$190  (via drill 0.61 pad 1.02)
  Top 0.406: 3.5,37.21 3.5,37.16 v3.17,36.83
  Bottom 0.406: J183. 3.49,37.15 v3.17,36.83
N$191  (via drill 0.61 pad 1.02)
  Top 0.406: 7.32,37.21 7.32,37.16 v6.99,36.83
  Bottom 0.406: J184. 7.3,37.15 v6.99,36.83
N$192  (via drill 0.61 pad 1.02)
  Top 0.406: 11.12,37.21 11.12,37.16 v10.79,36.83
  Bottom 0.406: J185. 11.11,37.15 v10.79,36.83
N$193  (via drill 0.61 pad 1.02)
  Top 0.305: 110.11,36.83 109.16,37.78 107.63,37.78 | 73.34,37.78 77.15,37.78 | 77.15,37.78 80.96,37.78 | 80.96,37.78 84.77,37.78 | 84.77,37.78 88.58,37.78 | 88.58,37.78 92.39,37.78 | 92.39,37.78 96.2,37.78 | 96.2,37.78 100.01,37.78 | 100.01,37.78 103.82,37.78 | 103.82,37.78 107.63,37.78 | v70.17,37.78 73.34,37.78 | 88.62,36.58 88.58,36.58 88.58,37.78 | 84.81,36.58 84.77,36.58 84.77,37.78 | 81,36.58 80.96,36.58 80.96,37.78 | 77.19,36.58 77.15,36.58 77.15,37.78 | 73.38,36.58 73.34,36.58 73.34,37.78 | 92.43,36.58 92.39,36.58 92.39,37.78 | 96.24,36.58 96.2,36.58 96.2,37.78 | 100.05,36.58 100.01,36.58 100.01,37.78 | 103.86,36.58 103.82,36.58 103.82,37.78 | 107.67,36.58 107.63,36.58 107.63,37.78
  Bottom 0.305: 5.21,37.15 5.08,37.15 5.08,35.56 8.89,35.56 | 8.89,35.56 12.7,35.56 | 12.7,35.56 16.51,35.56 | 16.51,35.56 20.32,35.56 | 20.32,35.56 24.13,35.56 | 24.13,35.56 27.94,35.56 | 27.94,35.56 31.75,35.56 | 31.75,35.56 35.56,35.56 | 35.56,35.56 39.37,35.56 | 39.37,35.56 43.18,35.56 | 43.18,35.56 46.99,35.56 | 46.99,35.56 50.8,35.56 | 50.8,35.56 54.61,35.56 | 54.61,35.56 58.42,35.56 | 58.42,35.56 62.23,35.56 | 9.02,37.15 8.89,37.15 8.89,35.56 | 12.83,37.15 12.7,37.15 12.7,35.56 | 16.64,37.15 16.51,37.15 16.51,35.56 | 24.26,37.15 24.13,37.15 24.13,35.56 | 20.45,37.15 20.32,37.15 20.32,35.56 | 28.07,37.15 27.94,37.15 27.94,35.56 | 31.88,37.15 31.75,37.15 31.75,35.56 | 39.5,37.15 39.37,37.15 39.37,35.56 | 43.31,37.15 43.18,37.15 43.18,35.56 | 47.12,37.15 46.99,37.15 46.99,35.56 | 50.93,37.15 50.8,37.15 50.8,35.56 | 54.74,37.15 54.61,37.15 54.61,35.56 | 58.55,37.15 58.42,37.15 58.42,35.56 | 62.36,37.15 62.23,37.15 62.23,35.56 | 35.69,37.15 35.56,37.15 35.56,35.56 | 62.23,35.56 67.94,35.56 v70.17,37.78
N$194  (via drill 0.61 pad 1.02)
  Top 0.406: 60.66,37.21 60.66,37.16 v60.33,36.83
  Bottom 0.406: J198. 60.64,37.15 v60.33,36.83
N$195  (via drill 0.61 pad 1.02)
  Top 0.406: 56.84,37.21 56.84,37.16 v56.52,36.83
  Bottom 0.406: J197. 56.83,37.15 v56.52,36.83
N$196  (via drill 0.61 pad 1.02)
  Top 0.406: 53.03,37.21 53.03,37.16 v52.7,36.83
  Bottom 0.406: J196. 53.02,37.15 v52.7,36.83
N$197  (via drill 0.61 pad 1.02)
  Top 0.406: 49.23,37.21 49.23,37.16 v48.9,36.83
  Bottom 0.406: J195. 49.21,37.15 v48.9,36.83
N$198  (via drill 0.61 pad 1.02)
  Top 0.406: 45.41,37.21 45.41,37.16 v45.09,36.83
  Bottom 0.406: J194. 45.4,37.15 v45.09,36.83
N$199  (via drill 0.61 pad 1.02)
  Top 0.406: 22.55,37.21 22.55,37.16 v22.23,36.83
  Bottom 0.406: J188. 22.54,37.15 v22.23,36.83
N$200  (via drill 0.61 pad 1.02)
  Top 0.406: 18.75,37.21 18.75,37.16 v18.41,36.83
  Bottom 0.406: J187. 18.73,37.15 v18.41,36.83
N$201  (via drill 0.61 pad 1.02)
  Top 0.406: 14.94,37.21 14.94,37.16 v14.61,36.83
  Bottom 0.406: J186. 14.92,37.15 v14.61,36.83
N$202  (via drill 0.61 pad 1.02)
  Top 0.406: 26.36,37.21 26.36,37.16 v26.04,36.83
  Bottom 0.406: J189. 26.35,37.15 v26.04,36.83
N$203  (via drill 0.61 pad 1.02)
  Top 0.406: 30.18,37.21 30.18,37.16 v29.84,36.83
  Bottom 0.406: J190. 30.16,37.15 v29.84,36.83
N$204  (via drill 0.61 pad 1.02)
  Top 0.406: 33.98,37.21 33.98,37.16 v33.66,36.83
  Bottom 0.406: J191. 33.97,37.15 v33.66,36.83
N$205  (via drill 0.61 pad 1.02)
  Top 0.406: 37.8,37.21 37.8,37.16 v37.47,36.83
  Bottom 0.406: J192. 37.78,37.15 v37.47,36.83
N$206  (via drill 0.61 pad 1.02)
  Top 0.406: 41.6,37.21 41.6,37.16 v41.27,36.83
  Bottom 0.406: J193. 41.59,37.15 v41.27,36.83
N$207  (via drill 0.61 pad 1.02)
  Top 0.305: 105.74,36.58 105.74,36.21 v105.41,35.88
  Bottom 0.305: J208. 105.73,36.2 v105.41,35.88
N$208  (via drill 0.61 pad 1.02)
  Top 0.305: 71.45,36.58 71.45,36.21 v71.12,35.88
  Bottom 0.305: J199. 71.44,36.2 v71.12,35.88
N$209  (via drill 0.61 pad 1.02)
  Top 0.305: 75.26,36.58 75.26,36.21 v74.93,35.88
  Bottom 0.305: J200. 75.25,36.2 v74.93,35.88
N$210  (via drill 0.61 pad 1.02)
  Top 0.305: 79.07,36.58 79.07,36.21 v78.74,35.88
  Bottom 0.305: J201. 79.06,36.2 v78.74,35.88
N$211  (via drill 0.61 pad 1.02)
  Top 0.305: 82.88,36.58 82.88,36.21 v82.55,35.88
  Bottom 0.305: J202. 82.87,36.2 v82.55,35.88
N$212  (via drill 0.61 pad 1.02)
  Top 0.305: 86.69,36.58 86.69,36.21 v86.36,35.88
  Bottom 0.305: J203. 86.68,36.2 v86.36,35.88
N$213  (via drill 0.61 pad 1.02)
  Top 0.305: 90.5,36.58 90.5,36.21 v90.17,35.88
  Bottom 0.305: J204. 90.49,36.2 v90.17,35.88
N$214  (via drill 0.61 pad 1.02)
  Top 0.305: 94.31,36.58 94.31,36.21 v93.98,35.88
  Bottom 0.305: J205. 94.3,36.2 v93.98,35.88
N$215  (via drill 0.61 pad 1.02)
  Top 0.305: 98.12,36.58 98.12,36.21 v97.79,35.88
  Bottom 0.305: J206. 98.11,36.2 v97.79,35.88
N$216  (via drill 0.61 pad 1.02)
  Top 0.305: 101.93,36.58 101.93,36.21 v101.6,35.88
  Bottom 0.305: J207. 101.92,36.2 v101.6,35.88
N$217  (via drill 0.61 pad 1.02)
  Top 0.406: 7.92,39.62 7.92,39.67 v8.26,40.01
  Bottom 0.406: J209. 7.94,39.69 v8.26,40.01
N$218  (via drill 0.61 pad 1.02)
  Top 0.406: 11.73,39.62 11.73,39.67 v12.06,40.01
  Bottom 0.406: J210. 11.75,39.69 v12.06,40.01
N$219  (via drill 0.61 pad 1.02)
  Top 0.406: 15.54,39.62 15.54,39.67 v15.88,40.01
  Bottom 0.406: J211. 15.56,39.69 v15.88,40.01
N$220  (via drill 0.61 pad 1.02)
  Top 0.305: 110.11,39.37 109.16,38.42 105.73,38.42 | 71.44,38.42 71.12,38.42 v70.17,39.37 | 71.44,38.42 75.25,38.42 | 75.25,38.42 79.06,38.42 | 79.06,38.42 82.87,38.42 | 82.87,38.42 86.68,38.42 | 86.68,38.42 90.49,38.42 | 90.49,38.42 94.3,38.42 | 94.3,38.42 98.11,38.42 | 98.11,38.42 101.92,38.42 | 101.92,38.42 105.73,38.42 | 71.4,39.62 71.44,39.62 71.44,38.42 | 75.21,39.62 75.25,39.62 75.25,38.42 | 79.02,39.62 79.06,39.62 79.06,38.42 | 82.83,39.62 82.87,39.62 82.87,38.42 | 86.64,39.62 86.68,39.62 86.68,38.42 | 90.45,39.62 90.49,39.62 90.49,38.42 | 94.26,39.62 94.3,39.62 94.3,38.42 | 98.07,39.62 98.11,39.62 98.11,38.42 | 101.88,39.62 101.92,39.62 101.92,38.42 | 105.69,39.62 105.73,39.62 105.73,38.42
  Bottom 0.305: 6.22,39.69 6.35,39.69 6.35,41.27 10.16,41.27 | 10.16,41.27 13.97,41.27 | 13.97,41.27 17.78,41.27 | 17.78,41.27 21.59,41.27 | 21.59,41.27 25.4,41.27 | 25.4,41.27 29.21,41.27 | 29.21,41.27 33.02,41.27 | 33.02,41.27 36.83,41.27 | 36.83,41.27 40.64,41.27 | 40.64,41.27 44.45,41.27 | 44.45,41.27 48.26,41.27 | 48.26,41.27 52.07,41.27 | 52.07,41.27 55.88,41.27 | 55.88,41.27 59.69,41.27 | 59.69,41.27 63.5,41.27 | 10.03,39.69 10.16,39.69 10.16,41.27 | 13.84,39.69 13.97,39.69 13.97,41.27 | 17.65,39.69 17.78,39.69 17.78,41.27 | 21.46,39.69 21.59,39.69 21.59,41.27 | 25.27,39.69 25.4,39.69 25.4,41.27 | 29.08,39.69 29.21,39.69 29.21,41.27 | 32.89,39.69 33.02,39.69 33.02,41.27 | 63.37,39.69 63.5,39.69 63.5,41.27 | 59.56,39.69 59.69,39.69 59.69,41.27 | 55.75,39.69 55.88,39.69 55.88,41.27 | 51.94,39.69 52.07,39.69 52.07,41.27 | 48.13,39.69 48.26,39.69 48.26,41.27 | 44.32,39.69 44.45,39.69 44.45,41.27 | 40.51,39.69 40.64,39.69 40.64,41.27 | 36.7,39.69 36.83,39.69 36.83,41.27 | 63.5,41.27 68.26,41.27 v70.17,39.37
N$221  (via drill 0.61 pad 1.02)
  Top 0.406: 65.08,39.62 65.08,39.67 v65.41,40.01
  Bottom 0.406: J224. 65.09,39.69 v65.41,40.01
N$222  (via drill 0.61 pad 1.02)
  Top 0.406: 61.27,39.62 61.27,39.67 v61.59,40.01
  Bottom 0.406: J223. 61.28,39.69 v61.59,40.01
N$223  (via drill 0.61 pad 1.02)
  Top 0.406: 57.45,39.62 57.45,39.67 v57.78,40.01
  Bottom 0.406: J222. 57.47,39.69 v57.78,40.01
N$224  (via drill 0.61 pad 1.02)
  Top 0.406: 53.65,39.62 53.65,39.67 v53.98,40.01
  Bottom 0.406: J221. 53.66,39.69 v53.98,40.01
N$225  (via drill 0.61 pad 1.02)
  Top 0.406: 49.84,39.62 49.84,39.67 v50.16,40.01
  Bottom 0.406: J220. 49.85,39.69 v50.16,40.01
N$226  (via drill 0.61 pad 1.02)
  Top 0.406: 26.98,39.62 26.98,39.67 v27.3,40.01
  Bottom 0.406: J214. 26.99,39.69 v27.3,40.01
N$227  (via drill 0.61 pad 1.02)
  Top 0.406: 23.16,39.62 23.16,39.67 v23.5,40.01
  Bottom 0.406: J213. 23.18,39.69 v23.5,40.01
N$228  (via drill 0.61 pad 1.02)
  Top 0.406: 19.36,39.62 19.36,39.67 v19.68,40.01
  Bottom 0.406: J212. 19.37,39.69 v19.68,40.01
N$229  (via drill 0.61 pad 1.02)
  Top 0.406: 30.79,39.62 30.79,39.67 v31.11,40.01
  Bottom 0.406: J215. 30.8,39.69 v31.11,40.01
N$230  (via drill 0.61 pad 1.02)
  Top 0.406: 34.59,39.62 34.59,39.67 v34.92,40.01
  Bottom 0.406: J216. 34.61,39.69 v34.92,40.01
N$231  (via drill 0.61 pad 1.02)
  Top 0.406: 38.41,39.62 38.41,39.67 v38.73,40.01
  Bottom 0.406: J217. 38.42,39.69 v38.73,40.01
N$232  (via drill 0.61 pad 1.02)
  Top 0.406: 42.22,39.62 42.22,39.67 v42.55,40.01
  Bottom 0.406: J218. 42.23,39.69 v42.55,40.01
N$233  (via drill 0.61 pad 1.02)
  Top 0.406: 46.02,39.62 46.02,39.67 v46.35,40.01
  Bottom 0.406: J219. 46.04,39.69 v46.35,40.01
N$234  (via drill 0.61 pad 1.02)
  Top 0.305: 107.62,39.62 107.62,39.99 v107.95,40.32
  Bottom 0.305: J234. 107.63,40.01 v107.95,40.32
N$235  (via drill 0.61 pad 1.02)
  Top 0.305: 73.33,39.62 73.33,39.99 v73.66,40.32
  Bottom 0.305: J225. 73.34,40.01 v73.66,40.32
N$236  (via drill 0.61 pad 1.02)
  Top 0.305: 77.14,39.62 77.14,39.99 v77.47,40.32
  Bottom 0.305: J226. 77.15,40.01 v77.47,40.32
N$237  (via drill 0.61 pad 1.02)
  Top 0.305: 80.95,39.62 80.95,39.99 v81.28,40.32
  Bottom 0.305: J227. 80.96,40.01 v81.28,40.32
N$238  (via drill 0.61 pad 1.02)
  Top 0.305: 84.76,39.62 84.76,39.99 v85.09,40.32
  Bottom 0.305: J228. 84.77,40.01 v85.09,40.32
N$239  (via drill 0.61 pad 1.02)
  Top 0.305: 88.57,39.62 88.57,39.99 v88.9,40.32
  Bottom 0.305: J229. 88.58,40.01 v88.9,40.32
N$240  (via drill 0.61 pad 1.02)
  Top 0.305: 92.38,39.62 92.38,39.99 v92.71,40.32
  Bottom 0.305: J230. 92.39,40.01 v92.71,40.32
N$241  (via drill 0.61 pad 1.02)
  Top 0.305: 96.19,39.62 96.19,39.99 v96.52,40.32
  Bottom 0.305: J231. 96.2,40.01 v96.52,40.32
N$242  (via drill 0.61 pad 1.02)
  Top 0.305: 100,39.62 100,39.99 v100.33,40.32
  Bottom 0.305: J232. 100.01,40.01 v100.33,40.32
N$243  (via drill 0.61 pad 1.02)
  Top 0.305: 103.81,39.62 103.81,39.99 v104.14,40.32
  Bottom 0.305: J233. 103.82,40.01 v104.14,40.32
N$244  (via drill 0.61 pad 1.02)
  Top 0.406: 3.5,45.47 3.5,45.41 v3.17,45.09
  Bottom 0.406: J235. 3.49,45.4 v3.17,45.09
N$245  (via drill 0.61 pad 1.02)
  Top 0.406: 7.32,45.47 7.32,45.41 v6.99,45.09
  Bottom 0.406: J236. 7.3,45.4 v6.99,45.09
N$246  (via drill 0.61 pad 1.02)
  Top 0.406: 11.12,45.47 11.12,45.41 v10.79,45.09
  Bottom 0.406: J237. 11.11,45.4 v10.79,45.09
N$247  (via drill 0.61 pad 1.02)
  Top 0.305: 110.11,45.09 109.16,46.04 107.63,46.04 | 73.34,46.04 77.15,46.04 | 77.15,46.04 80.96,46.04 | 80.96,46.04 84.77,46.04 | 84.77,46.04 88.58,46.04 | 88.58,46.04 92.39,46.04 | 92.39,46.04 96.2,46.04 | 96.2,46.04 100.01,46.04 | 100.01,46.04 103.82,46.04 | 103.82,46.04 107.63,46.04 | v70.17,46.04 73.34,46.04 | 73.38,44.83 73.34,44.83 73.34,46.04 | 77.19,44.83 77.15,44.83 77.15,46.04 | 81,44.83 80.96,44.83 80.96,46.04 | 84.81,44.83 84.77,44.83 84.77,46.04 | 88.62,44.83 88.58,44.83 88.58,46.04 | 92.43,44.83 92.39,44.83 92.39,46.04 | 96.24,44.83 96.2,44.83 96.2,46.04 | 100.05,44.83 100.01,44.83 100.01,46.04 | 103.86,44.83 103.82,44.83 103.82,46.04 | 107.67,44.83 107.63,44.83 107.63,46.04
  Bottom 0.305: 5.21,45.4 5.08,45.4 5.08,43.81 8.89,43.81 | 8.89,43.81 12.7,43.81 | 12.7,43.81 16.51,43.81 | 16.51,43.81 20.32,43.81 | 20.32,43.81 24.13,43.81 | 24.13,43.81 27.94,43.81 | 27.94,43.81 31.75,43.81 | 31.75,43.81 35.56,43.81 | 35.56,43.81 39.37,43.81 | 39.37,43.81 43.18,43.81 | 43.18,43.81 46.99,43.81 | 46.99,43.81 50.8,43.81 | 50.8,43.81 54.61,43.81 | 54.61,43.81 58.42,43.81 | 58.42,43.81 62.23,43.81 | 9.02,45.4 8.89,45.4 8.89,43.81 | 12.83,45.4 12.7,45.4 12.7,43.81 | 16.64,45.4 16.51,45.4 16.51,43.81 | 20.45,45.4 20.32,45.4 20.32,43.81 | 24.26,45.4 24.13,45.4 24.13,43.81 | 28.07,45.4 27.94,45.4 27.94,43.81 | 31.88,45.4 31.75,45.4 31.75,43.81 | 35.69,45.4 35.56,45.4 35.56,43.81 | 39.5,45.4 39.37,45.4 39.37,43.81 | 43.31,45.4 43.18,45.4 43.18,43.81 | 47.12,45.4 46.99,45.4 46.99,43.81 | 50.93,45.4 50.8,45.4 50.8,43.81 | 54.74,45.4 54.61,45.4 54.61,43.81 | 62.36,45.4 62.23,45.4 62.23,43.81 | 58.55,45.4 58.42,45.4 58.42,43.81 | 62.23,43.81 67.94,43.81 v70.17,46.04
N$248  (via drill 0.61 pad 1.02)
  Top 0.406: 60.66,45.47 60.66,45.41 v60.33,45.09
  Bottom 0.406: J250. 60.64,45.4 v60.33,45.09
N$249  (via drill 0.61 pad 1.02)
  Top 0.406: 56.84,45.47 56.84,45.41 v56.52,45.09
  Bottom 0.406: J249. 56.83,45.4 v56.52,45.09
N$250  (via drill 0.61 pad 1.02)
  Top 0.406: 53.03,45.47 53.03,45.41 v52.7,45.09
  Bottom 0.406: J248. 53.02,45.4 v52.7,45.09
N$251  (via drill 0.61 pad 1.02)
  Top 0.406: 49.23,45.47 49.23,45.41 v48.9,45.09
  Bottom 0.406: J247. 49.21,45.4 v48.9,45.09
N$252  (via drill 0.61 pad 1.02)
  Top 0.406: 45.41,45.47 45.41,45.41 v45.09,45.09
  Bottom 0.406: J246. 45.4,45.4 v45.09,45.09
N$253  (via drill 0.61 pad 1.02)
  Top 0.406: 22.55,45.47 22.55,45.41 v22.23,45.09
  Bottom 0.406: J240. 22.54,45.4 v22.23,45.09
N$254  (via drill 0.61 pad 1.02)
  Top 0.406: 18.75,45.47 18.75,45.41 v18.41,45.09
  Bottom 0.406: J239. 18.73,45.4 v18.41,45.09
N$255  (via drill 0.61 pad 1.02)
  Top 0.406: 14.94,45.47 14.94,45.41 v14.61,45.09
  Bottom 0.406: J238. 14.92,45.4 v14.61,45.09
N$256  (via drill 0.61 pad 1.02)
  Top 0.406: 26.36,45.47 26.36,45.41 v26.04,45.09
  Bottom 0.406: J241. 26.35,45.4 v26.04,45.09
N$257  (via drill 0.61 pad 1.02)
  Top 0.406: 30.18,45.47 30.18,45.41 v29.84,45.09
  Bottom 0.406: J242. 30.16,45.4 v29.84,45.09
N$258  (via drill 0.61 pad 1.02)
  Top 0.406: 33.98,45.47 33.98,45.41 v33.66,45.09
  Bottom 0.406: J243. 33.97,45.4 v33.66,45.09
N$259  (via drill 0.61 pad 1.02)
  Top 0.406: 37.8,45.47 37.8,45.41 v37.47,45.09
  Bottom 0.406: J244. 37.78,45.4 v37.47,45.09
N$260  (via drill 0.61 pad 1.02)
  Top 0.406: 41.6,45.47 41.6,45.41 v41.27,45.09
  Bottom 0.406: J245. 41.59,45.4 v41.27,45.09
N$261  (via drill 0.61 pad 1.02)
  Top 0.305: 105.74,44.83 105.74,44.46 v105.41,44.13
  Bottom 0.305: J260. 105.73,44.45 v105.41,44.13
N$262  (via drill 0.61 pad 1.02)
  Top 0.305: 71.45,44.83 71.45,44.46 v71.12,44.13
  Bottom 0.305: J251. 71.44,44.45 v71.12,44.13
N$263  (via drill 0.61 pad 1.02)
  Top 0.305: 75.26,44.83 75.26,44.46 v74.93,44.13
  Bottom 0.305: J252. 75.25,44.45 v74.93,44.13
N$264  (via drill 0.61 pad 1.02)
  Top 0.305: 79.07,44.83 79.07,44.46 v78.74,44.13
  Bottom 0.305: J253. 79.06,44.45 v78.74,44.13
N$265  (via drill 0.61 pad 1.02)
  Top 0.305: 82.88,44.83 82.88,44.46 v82.55,44.13
  Bottom 0.305: J254. 82.87,44.45 v82.55,44.13
N$266  (via drill 0.61 pad 1.02)
  Top 0.305: 86.69,44.83 86.69,44.46 v86.36,44.13
  Bottom 0.305: J255. 86.68,44.45 v86.36,44.13
N$267  (via drill 0.61 pad 1.02)
  Top 0.305: v90.17,44.13 90.49,44.13 90.5,44.15 90.5,44.83
  Bottom 0.305: J256. 90.49,44.45 v90.17,44.13
N$268  (via drill 0.61 pad 1.02)
  Top 0.305: 94.31,44.83 94.31,44.46 v93.98,44.13
  Bottom 0.305: J257. 94.3,44.45 v93.98,44.13
N$269  (via drill 0.61 pad 1.02)
  Top 0.305: 98.12,44.83 98.12,44.46 v97.79,44.13
  Bottom 0.305: J258. 98.11,44.45 v97.79,44.13
N$270  (via drill 0.61 pad 1.02)
  Top 0.305: 101.93,44.83 101.93,44.46 v101.6,44.13
  Bottom 0.305: J259. 101.92,44.45 v101.6,44.13
N$271  (via drill 0.61 pad 1.02)
  Top 0.406: 7.92,47.88 7.92,47.93 v8.26,48.26
  Bottom 0.406: J261. 7.94,47.94 v8.26,48.26
N$272  (via drill 0.61 pad 1.02)
  Top 0.406: 11.73,47.88 11.73,47.93 v12.06,48.26
  Bottom 0.406: J262. 11.75,47.94 v12.06,48.26
N$273  (via drill 0.61 pad 1.02)
  Top 0.406: 15.54,47.88 15.54,47.93 v15.88,48.26
  Bottom 0.406: J263. 15.56,47.94 v15.88,48.26
N$274  (via drill 0.61 pad 1.02)
  Top 0.305: 110.11,47.62 109.16,46.67 105.73,46.67 | 71.44,46.67 71.12,46.67 v70.17,47.62 | 71.44,46.67 75.25,46.67 | 75.25,46.67 79.06,46.67 | 79.06,46.67 82.87,46.67 | 82.87,46.67 86.68,46.67 | 86.68,46.67 90.49,46.67 | 90.49,46.67 94.3,46.67 | 94.3,46.67 98.11,46.67 | 98.11,46.67 101.92,46.67 | 101.92,46.67 105.73,46.67 | 71.4,47.88 71.44,47.88 71.44,46.67 | 75.21,47.88 75.25,47.88 75.25,46.67 | 79.02,47.88 79.06,47.88 79.06,46.67 | 82.83,47.88 82.87,47.88 82.87,46.67 | 86.64,47.88 86.68,47.88 86.68,46.67 | 90.45,47.88 90.49,47.88 90.49,46.67 | 94.26,47.88 94.3,47.88 94.3,46.67 | 98.07,47.88 98.11,47.88 98.11,46.67 | 101.88,47.88 101.92,47.88 101.92,46.67 | 105.69,47.88 105.73,47.88 105.73,46.67
  Bottom 0.305: 6.22,47.94 6.35,47.94 6.35,49.53 10.16,49.53 | 10.16,49.53 13.97,49.53 | 13.97,49.53 17.78,49.53 | 17.78,49.53 21.59,49.53 | 21.59,49.53 25.4,49.53 | 25.4,49.53 29.21,49.53 | 29.21,49.53 33.02,49.53 | 33.02,49.53 36.83,49.53 | 36.83,49.53 40.64,49.53 | 40.64,49.53 44.45,49.53 | 44.45,49.53 48.26,49.53 | 48.26,49.53 52.07,49.53 | 52.07,49.53 55.88,49.53 | 55.88,49.53 59.69,49.53 | 59.69,49.53 63.5,49.53 | 29.08,47.94 29.21,47.94 29.21,49.53 | 25.27,47.94 25.4,47.94 25.4,49.53 | 21.46,47.94 21.59,47.94 21.59,49.53 | 17.65,47.94 17.78,47.94 17.78,49.53 | 13.84,47.94 13.97,47.94 13.97,49.53 | 10.03,47.94 10.16,47.94 10.16,49.53 | 63.37,47.94 63.5,47.94 63.5,49.53 | 59.56,47.94 59.69,47.94 59.69,49.53 | 55.75,47.94 55.88,47.94 55.88,49.53 | 51.94,47.94 52.07,47.94 52.07,49.53 | 48.13,47.94 48.26,47.94 48.26,49.53 | 44.32,47.94 44.45,47.94 44.45,49.53 | 40.51,47.94 40.64,47.94 40.64,49.53 | 36.7,47.94 36.83,47.94 36.83,49.53 | 32.89,47.94 33.02,47.94 33.02,49.53 | 63.5,49.53 68.26,49.53 v70.17,47.62
N$275  (via drill 0.61 pad 1.02)
  Top 0.406: 65.08,47.88 65.08,47.93 v65.41,48.26
  Bottom 0.406: J276. 65.09,47.94 v65.41,48.26
N$276  (via drill 0.61 pad 1.02)
  Top 0.406: 61.27,47.88 61.27,47.93 v61.59,48.26
  Bottom 0.406: J275. 61.28,47.94 v61.59,48.26
N$277  (via drill 0.61 pad 1.02)
  Top 0.406: 57.45,47.88 57.45,47.93 v57.78,48.26
  Bottom 0.406: J274. 57.47,47.94 v57.78,48.26
N$278  (via drill 0.61 pad 1.02)
  Top 0.406: 53.65,47.88 53.65,47.93 v53.98,48.26
  Bottom 0.406: J273. 53.66,47.94 v53.98,48.26
N$279  (via drill 0.61 pad 1.02)
  Top 0.406: 49.84,47.88 49.84,47.93 v50.16,48.26
  Bottom 0.406: J272. 49.85,47.94 v50.16,48.26
N$280  (via drill 0.61 pad 1.02)
  Top 0.406: 26.98,47.88 26.98,47.93 v27.3,48.26
  Bottom 0.406: J266. 26.99,47.94 v27.3,48.26
N$281  (via drill 0.61 pad 1.02)
  Top 0.406: 23.16,47.88 23.16,47.93 v23.5,48.26
  Bottom 0.406: J265. 23.18,47.94 v23.5,48.26
N$282  (via drill 0.61 pad 1.02)
  Top 0.406: 19.36,47.88 19.36,47.93 v19.68,48.26
  Bottom 0.406: J264. 19.37,47.94 v19.68,48.26
N$283  (via drill 0.61 pad 1.02)
  Top 0.406: 30.79,47.88 30.79,47.93 v31.11,48.26
  Bottom 0.406: J267. 30.8,47.94 v31.11,48.26
N$284  (via drill 0.61 pad 1.02)
  Top 0.406: 34.59,47.88 34.59,47.93 v34.92,48.26
  Bottom 0.406: J268. 34.61,47.94 v34.92,48.26
N$285  (via drill 0.61 pad 1.02)
  Top 0.406: 38.41,47.88 38.41,47.93 v38.73,48.26
  Bottom 0.406: J269. 38.42,47.94 v38.73,48.26
N$286  (via drill 0.61 pad 1.02)
  Top 0.406: 42.22,47.88 42.22,47.93 v42.55,48.26
  Bottom 0.406: J270. 42.23,47.94 v42.55,48.26
N$287  (via drill 0.61 pad 1.02)
  Top 0.406: 46.02,47.88 46.02,47.93 v46.35,48.26
  Bottom 0.406: J271. 46.04,47.94 v46.35,48.26
N$288  (via drill 0.61 pad 1.02)
  Top 0.305: 107.62,47.88 107.62,48.25 v107.95,48.58
  Bottom 0.305: J286. 107.63,48.26 v107.95,48.58
N$289  (via drill 0.61 pad 1.02)
  Top 0.305: 73.33,47.88 73.33,48.25 v73.66,48.58
  Bottom 0.305: J277. 73.34,48.26 v73.66,48.58
N$290  (via drill 0.61 pad 1.02)
  Top 0.305: 77.14,47.88 77.14,48.25 v77.47,48.58
  Bottom 0.305: J278. 77.15,48.26 v77.47,48.58
N$291  (via drill 0.61 pad 1.02)
  Top 0.305: 80.95,47.88 80.95,48.25 v81.28,48.58
  Bottom 0.305: J279. 80.96,48.26 v81.28,48.58
N$292  (via drill 0.61 pad 1.02)
  Top 0.305: 84.76,47.88 84.76,48.25 v85.09,48.58
  Bottom 0.305: J280. 84.77,48.26 v85.09,48.58
N$293  (via drill 0.61 pad 1.02)
  Top 0.305: 88.57,47.88 88.57,48.25 v88.9,48.58
  Bottom 0.305: J281. 88.58,48.26 v88.9,48.58
N$294  (via drill 0.61 pad 1.02)
  Top 0.305: 92.38,47.88 92.38,48.25 v92.71,48.58
  Bottom 0.305: J282. 92.39,48.26 v92.71,48.58
N$295  (via drill 0.61 pad 1.02)
  Top 0.305: 96.19,47.88 96.19,48.25 v96.52,48.58
  Bottom 0.305: J283. 96.2,48.26 v96.52,48.58
N$296  (via drill 0.61 pad 1.02)
  Top 0.305: 100,47.88 100,48.25 v100.33,48.58
  Bottom 0.305: J284. 100.01,48.26 v100.33,48.58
